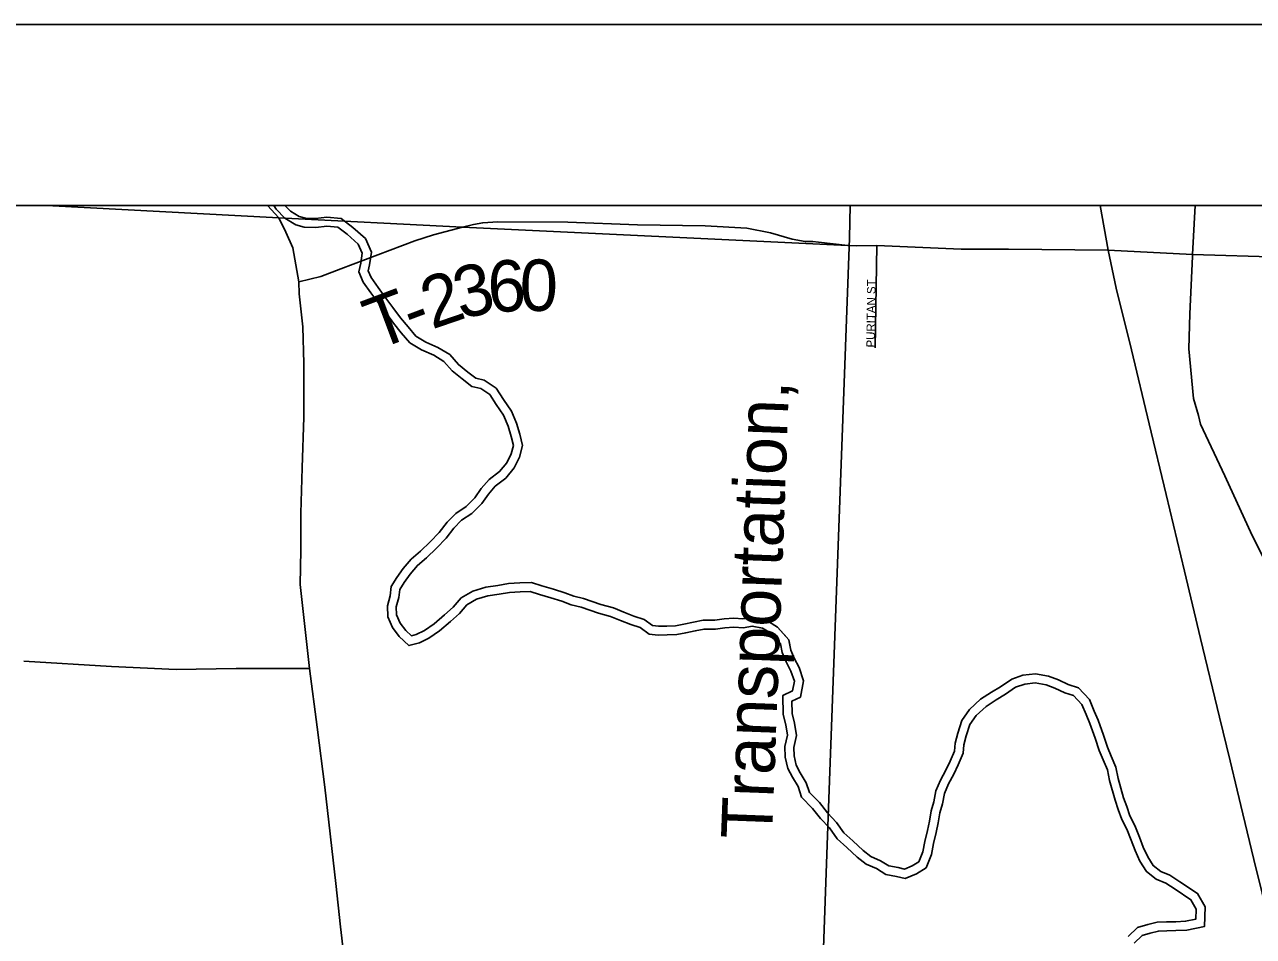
# Model space of a CAD drawing. Extents: x -22 to 431, y -18 to 160.
# Drawn here: x 323.477 to 324.836, y 159.112 to 160.12 of the extents above; entities that cross this region are included whole.
import ezdxf

# ---------------------------------------------------------------- set-up
doc = ezdxf.new("R2010")
doc.units = 0
for name, color, linetype in [('GM_X_Adjacent_County_Text', 7, 'Continuous'), ('GM_X_City_Street_Text', 7, 'Continuous'), ('GM_X_County_ROW', 7, 'Continuous'), ('GM_X_County_Subdivision', 7, 'Continuous'), ('GM_X_Major_Lake', 7, 'Continuous'), ('GM_X_Major_River_Text', 7, 'Continuous'), ('GM_X_Minor_River_Text', 7, 'Continuous'), ('GM_X_Rail_Line', 7, 'Continuous'), ('GM_X_Section', 7, 'Continuous'), ('GM_X_State_Location', 7, 'Continuous'), ('GM_X_Township_ROW', 7, 'Continuous'), ('GM_X_Township_Subdivision_Text', 7, 'Continuous')]:
    doc.layers.add(name, color=color, linetype=linetype)

msp = doc.modelspace()

# ---------------------------------------------------------------- linework, layer by layer
at = {"layer": 'GM_X_Adjacent_County_Text'}
for points in [[(324.7685, 159.8633), (324.7687, 159.8658), (324.7716, 159.9199)], [(325.1477, 159.1289), (325.1213, 159.1641), (325.057, 159.252), (325.0057, 159.3213), (324.9662, 159.3699), (324.9498, 159.3902), (324.9293, 159.4116), (324.9095, 159.4278), (324.896, 159.4378), (324.8897, 159.4458), (324.8837, 159.4573), (324.8346, 159.5549), (324.8044, 159.6209), (324.7775, 159.6781), (324.7754, 159.6876), (324.7699, 159.7066), (324.7645, 159.7613), (324.7657, 159.7999), (324.7685, 159.8633)]]:
    msp.add_lwpolyline(points, dxfattribs=at)
at = {"layer": 'GM_X_County_ROW'}
msp.add_lwpolyline([(323.8332, 159.0653), (323.8264, 159.1222), (323.8213, 159.1701), (323.8091, 159.2765), (323.8005, 159.3428), (323.792, 159.4078), (323.7817, 159.5007), (323.7825, 159.5388), (323.7825, 159.5795), (323.7841, 159.6298), (323.7859, 159.6857), (323.7859, 159.7452), (323.7848, 159.7857), (323.7809, 159.8223), (323.7804, 159.8356), (323.7739, 159.8729), (323.7661, 159.8902), (323.7583, 159.9062), (323.7457, 159.9199)], dxfattribs=at)
at = {"layer": 'GM_X_Major_River_Text'}
for p, q in [((323.5012, 159.9199), (323.7583, 159.9062)), ((323.7583, 159.9062), (323.9614, 159.896)), ((323.9614, 159.896), (324.3875, 159.8756)), ((324.3971, 159.8752), (324.3875, 159.8756)), ((324.3875, 159.8756), (324.3971, 159.8752)), ((324.4195, 159.8758), (324.3971, 159.8752)), ((324.4195, 159.8758), (324.513, 159.8717)), ((324.565, 159.8717), (324.513, 159.8717)), ((324.6754, 159.8703), (324.565, 159.8717)), ((324.7687, 159.8658), (324.6754, 159.8703)), ((324.7687, 159.8658), (325.4291, 159.8451))]:
    msp.add_line(p, q, dxfattribs=at)
at = {"layer": 'GM_X_Minor_River_Text'}
for points in [[(323.7804, 159.8356), (323.8048, 159.8412), (323.8268, 159.8498), (323.9088, 159.8809), (323.9293, 159.8876), (323.9614, 159.896), (323.9734, 159.8988), (323.9838, 159.9008), (324.0004, 159.9019), (324.0777, 159.9014), (324.1549, 159.8986), (324.2297, 159.8975), (324.2757, 159.8948), (324.302, 159.8895), (324.3258, 159.8826), (324.3405, 159.8802), (324.3487, 159.88), (324.3551, 159.8793), (324.3875, 159.8756), (324.3879, 159.8755)], [(324.3879, 159.8755), (324.3971, 159.8752), (324.4195, 159.8758), (324.513, 159.8717), (324.565, 159.8717)], [(323.4763, 159.416), (323.5733, 159.4102), (323.6446, 159.4068), (323.7112, 159.4078), (323.792, 159.4078)]]:
    msp.add_lwpolyline(points, dxfattribs=at)
at = {"layer": 'GM_X_Rail_Line'}
for points in [[(324.8245, 159.247), (324.8182, 159.2732), (324.8103, 159.3059), (324.7987, 159.3539), (324.7775, 159.4409), (324.7599, 159.5155), (324.7395, 159.6003), (324.7207, 159.6783), (324.7011, 159.7601), (324.6843, 159.8283), (324.6754, 159.8703), (324.6667, 159.9199)], [(325.0236, 158.268), (325.0178, 158.3353), (325.0111, 158.3892), (325.0083, 158.4105), (325.0062, 158.4257), (324.9949, 158.5051), (324.9839, 158.5695), (324.9706, 158.6339), (324.9581, 158.6937), (324.9437, 158.7535), (324.9274, 158.819), (324.909, 158.8939), (324.8914, 158.9704), (324.8757, 159.0378), (324.855, 159.1222), (324.8366, 159.1967), (324.8245, 159.247)]]:
    msp.add_lwpolyline(points, dxfattribs=at)
at = {"layer": 'GM_X_Section'}
msp.add_line((319.5549, 159.9199), (331.7949, 159.9199), dxfattribs=at)
msp.add_lwpolyline([(319.3549, 160.1199), (331.9949, 160.1199), (331.9949, 147.4799), (319.3549, 147.4799)], close=True, dxfattribs=at)
at = {"layer": 'GM_X_State_Location'}
msp.add_lwpolyline([(324.3484, 158.7568), (324.3659, 159.2438), (324.3892, 159.8839), (324.3902, 159.9199)], dxfattribs=at)
at = {"layer": 'GM_X_Township_ROW'}
msp.add_lwpolyline([(324.4179, 159.7623), (324.4195, 159.8758)], dxfattribs=at)
at = {"layer": 'GM_X_Township_Subdivision_Text'}
for points in [[(324.313, 159.4352), (324.3034, 159.4461), (324.2932, 159.4524), (324.2818, 159.4546), (324.272, 159.453), (324.2614, 159.4536), (324.2516, 159.4528), (324.241, 159.4515), (324.2285, 159.4514), (324.2187, 159.4494), (324.2082, 159.4474), (324.1983, 159.4454), (324.1878, 159.4449), (324.1776, 159.4448), (324.1677, 159.4458), (324.1578, 159.4533), (324.1476, 159.4566), (324.1362, 159.461), (324.1252, 159.4655), (324.1116, 159.4691), (324.0926, 159.4757), (324.0816, 159.4783), (324.0714, 159.4823), (324.0592, 159.486), (324.0464, 159.4897), (324.0361, 159.493), (324.0252, 159.4928), (324.0135, 159.492), (324.0018, 159.4899), (323.9893, 159.4883), (323.9769, 159.4844), (323.9663, 159.4782), (323.9581, 159.4686), (323.948, 159.4598), (323.936, 159.4494), (323.9243, 159.4414), (323.9138, 159.4363), (323.9021, 159.4332), (323.8914, 159.4433), (323.8838, 159.4531), (323.8787, 159.4651), (323.8783, 159.4773), (323.8812, 159.4883), (323.8826, 159.4985), (323.8886, 159.5085), (323.8957, 159.5184), (323.9046, 159.5287), (323.9148, 159.5375), (323.9256, 159.5479), (323.9357, 159.5582), (323.9443, 159.5697), (323.9541, 159.5793), (323.9654, 159.587), (323.9751, 159.5966), (323.9822, 159.6069), (323.9908, 159.6168), (324.0024, 159.6257), (324.0103, 159.6352), (324.0151, 159.6451), (324.0177, 159.6546), (324.0153, 159.6645), (324.0118, 159.6758), (324.0068, 159.6879), (323.9987, 159.6999), (323.9915, 159.7108), (323.9816, 159.7176), (323.9717, 159.7197), (323.9611, 159.728), (323.95, 159.7369), (323.9409, 159.7475), (323.9295, 159.7542), (323.9162, 159.7601), (323.9032, 159.7679), (323.8937, 159.7792), (323.8849, 159.7897), (323.8765, 159.8014), (323.8688, 159.8115), (323.86, 159.8232), (323.8516, 159.8352), (323.8466, 159.8465), (323.8488, 159.856), (323.8506, 159.8671), (323.8459, 159.8772), (323.8338, 159.8881), (323.8235, 159.896), (323.8114, 159.897), (323.7993, 159.8957), (323.7864, 159.8959), (323.777, 159.8985), (323.7648, 159.9059), (323.7553, 159.9157), (323.7528, 159.9199)], [(324.3204, 159.4417), (324.3098, 159.4537), (324.2968, 159.4618), (324.2819, 159.4646), (324.2715, 159.4629), (324.2613, 159.4635), (324.2506, 159.4626), (324.2404, 159.4613), (324.2275, 159.4612), (324.2168, 159.459), (324.2063, 159.457), (324.1971, 159.4552), (324.1875, 159.4547), (324.178, 159.4546), (324.1715, 159.4553), (324.1624, 159.4621), (324.1509, 159.4659), (324.1398, 159.4702), (324.1283, 159.4748), (324.1145, 159.4785), (324.0953, 159.4852), (324.0846, 159.4877), (324.0746, 159.4916), (324.062, 159.4954), (324.0492, 159.4991), (324.0376, 159.5028), (324.0247, 159.5027), (324.0122, 159.5017), (324.0003, 159.4997), (323.9872, 159.4979), (323.9728, 159.4934), (323.9599, 159.4859), (323.9511, 159.4756), (323.9415, 159.4672), (323.9299, 159.4572), (323.9194, 159.4499), (323.9103, 159.4456), (323.9048, 159.4441), (323.8987, 159.4499), (323.8923, 159.4581), (323.8885, 159.4673), (323.8881, 159.4762), (323.8908, 159.4863), (323.8921, 159.4952), (323.8968, 159.5031), (323.9034, 159.5123), (323.9116, 159.5218), (323.9214, 159.5303), (323.9325, 159.5409), (323.9432, 159.5518), (323.9518, 159.5632), (323.9603, 159.5717), (323.9716, 159.5794), (323.9827, 159.5902), (323.99, 159.6008), (323.9976, 159.6096), (324.0093, 159.6185), (324.0186, 159.6299), (324.0244, 159.6417), (324.0278, 159.6545), (324.0248, 159.6671), (324.0211, 159.6791), (324.0155, 159.6925), (324.0069, 159.7054), (323.9986, 159.7179), (323.9855, 159.7268), (323.976, 159.7289), (323.9672, 159.7357), (323.9569, 159.744), (323.9472, 159.7551), (323.934, 159.7629), (323.9207, 159.7688), (323.9097, 159.7755), (323.9012, 159.7855), (323.8927, 159.7957), (323.8844, 159.8072), (323.8767, 159.8174), (323.868, 159.829), (323.8602, 159.8401), (323.8569, 159.8475), (323.8584, 159.8541), (323.8608, 159.8684), (323.854, 159.8832), (323.84, 159.8957), (323.8272, 159.9055), (323.8113, 159.9068), (323.7989, 159.9055), (323.7878, 159.9058), (323.7809, 159.9076), (323.771, 159.9137), (323.7649, 159.9199)], [(324.3221, 159.4397), (324.3098, 159.4537), (324.2968, 159.4618), (324.2819, 159.4646), (324.2715, 159.4629), (324.2613, 159.4635), (324.2506, 159.4626), (324.2404, 159.4613), (324.2275, 159.4612), (324.2168, 159.459), (324.2063, 159.457), (324.1971, 159.4552), (324.1875, 159.4547), (324.178, 159.4546), (324.1715, 159.4553), (324.1624, 159.4621), (324.1509, 159.4659), (324.1398, 159.4702), (324.1283, 159.4748), (324.1145, 159.4785), (324.0953, 159.4852), (324.0846, 159.4877), (324.0746, 159.4916), (324.062, 159.4954), (324.0492, 159.4991), (324.0376, 159.5028), (324.0247, 159.5027), (324.0122, 159.5017), (324.0003, 159.4997), (323.9872, 159.4979), (323.9728, 159.4934), (323.9599, 159.4859), (323.9511, 159.4756), (323.9415, 159.4672), (323.9299, 159.4572), (323.9194, 159.4499), (323.9103, 159.4456), (323.9048, 159.4441), (323.8987, 159.4499), (323.8923, 159.4581), (323.8885, 159.4673), (323.8881, 159.4762), (323.8908, 159.4863), (323.8921, 159.4952), (323.8968, 159.5031), (323.9034, 159.5123), (323.9116, 159.5218), (323.9214, 159.5303), (323.9325, 159.5409), (323.9432, 159.5518), (323.9518, 159.5632), (323.9603, 159.5717), (323.9716, 159.5794), (323.9827, 159.5902), (323.99, 159.6008), (323.9976, 159.6096), (324.0093, 159.6185), (324.0186, 159.6299), (324.0244, 159.6417), (324.0278, 159.6545), (324.0248, 159.6671), (324.0211, 159.6791), (324.0155, 159.6925), (324.0069, 159.7054), (323.9986, 159.7179), (323.9855, 159.7268), (323.976, 159.7289), (323.9672, 159.7357), (323.9569, 159.744), (323.9472, 159.7551), (323.934, 159.7629), (323.9207, 159.7688), (323.9097, 159.7755), (323.9012, 159.7855), (323.8927, 159.7957), (323.8844, 159.8072), (323.8767, 159.8174), (323.868, 159.829), (323.8602, 159.8401), (323.8569, 159.8475), (323.8584, 159.8541), (323.8608, 159.8684), (323.854, 159.8832), (323.84, 159.8957), (323.8272, 159.9055), (323.8113, 159.9068), (323.7989, 159.9055), (323.7878, 159.9058), (323.7809, 159.9076), (323.771, 159.9137), (323.7649, 159.9199)], [(324.6977, 159.1113), (324.7078, 159.1213), (324.7191, 159.1248), (324.7297, 159.1272), (324.7399, 159.1277), (324.7501, 159.1278), (324.761, 159.1283), (324.7724, 159.1307), (324.7726, 159.1417), (324.7669, 159.1522), (324.7494, 159.1638), (324.7391, 159.1705), (324.7285, 159.175), (324.7178, 159.1832), (324.7105, 159.1949), (324.7052, 159.2066), (324.7009, 159.2179), (324.6959, 159.2303), (324.6905, 159.2409), (324.6866, 159.2519), (324.6831, 159.2621), (324.6769, 159.284), (324.6745, 159.2957), (324.6699, 159.307), (324.6656, 159.3172), (324.6609, 159.3308), (324.6551, 159.3471), (324.6509, 159.3569), (324.6462, 159.3682), (324.6371, 159.378), (324.6276, 159.3809), (324.6166, 159.3861), (324.6067, 159.3898), (324.5946, 159.3919), (324.5833, 159.3907), (324.5731, 159.3871), (324.5618, 159.3794), (324.5517, 159.3733), (324.5404, 159.3659), (324.5295, 159.356), (324.5224, 159.346), (324.5184, 159.3335), (324.5158, 159.3236), (324.5152, 159.3141), (324.5096, 159.3012), (324.5048, 159.2909), (324.4988, 159.2802), (324.4944, 159.2696), (324.4922, 159.2582), (324.4893, 159.2483), (324.4875, 159.2373), (324.4853, 159.2266), (324.4824, 159.2145), (324.4799, 159.2023), (324.474, 159.1875), (324.4634, 159.1809), (324.451, 159.1755), (324.4412, 159.178), (324.4294, 159.1802), (324.4192, 159.1865), (324.4078, 159.1913), (324.3979, 159.1992), (324.3864, 159.21), (324.3758, 159.2194), (324.3673, 159.2315), (324.3574, 159.242), (324.3486, 159.2532), (324.3364, 159.2656), (324.3325, 159.2773), (324.3264, 159.2875), (324.321, 159.2973), (324.3183, 159.3098), (324.3178, 159.3215), (324.3207, 159.3341), (324.3191, 159.3454), (324.3159, 159.3568), (324.3158, 159.378), (324.3263, 159.383), (324.3285, 159.3937), (324.3246, 159.405), (324.3192, 159.4152), (324.315, 159.4254), (324.313, 159.4352)], [(324.7043, 159.104), (324.713, 159.1126), (324.7217, 159.1153), (324.731, 159.1174), (324.7402, 159.1179), (324.7504, 159.118), (324.7623, 159.1185), (324.782, 159.1227), (324.7825, 159.1441), (324.7743, 159.1591), (324.7548, 159.172), (324.7437, 159.1792), (324.7335, 159.1835), (324.7252, 159.1899), (324.7192, 159.1995), (324.7142, 159.2104), (324.7101, 159.2215), (324.7048, 159.2344), (324.6995, 159.2448), (324.6959, 159.2551), (324.6925, 159.265), (324.6864, 159.2863), (324.6839, 159.2986), (324.6789, 159.3108), (324.6748, 159.3207), (324.6702, 159.3341), (324.6643, 159.3507), (324.6599, 159.3607), (324.6547, 159.3736), (324.6425, 159.3866), (324.6312, 159.3901), (324.6204, 159.3952), (324.6093, 159.3993), (324.5949, 159.4019), (324.5811, 159.4003), (324.5687, 159.396), (324.5565, 159.3877), (324.5465, 159.3816), (324.5344, 159.3738), (324.5221, 159.3625), (324.5136, 159.3505), (324.509, 159.3362), (324.5061, 159.3252), (324.5055, 159.3165), (324.5006, 159.3052), (324.496, 159.2954), (324.49, 159.2845), (324.4849, 159.2724), (324.4827, 159.2605), (324.4797, 159.2505), (324.4778, 159.239), (324.4757, 159.2288), (324.4728, 159.2166), (324.4704, 159.2052), (324.466, 159.1941), (324.4588, 159.1896), (324.4502, 159.1858), (324.4433, 159.1876), (324.433, 159.1895), (324.4237, 159.1953), (324.4128, 159.1999), (324.4043, 159.2066), (324.3931, 159.2173), (324.3831, 159.226), (324.375, 159.2377), (324.3649, 159.2484), (324.356, 159.2597), (324.345, 159.2709), (324.3415, 159.2815), (324.3349, 159.2924), (324.3303, 159.3008), (324.328, 159.3111), (324.3277, 159.3206), (324.3307, 159.3336), (324.3287, 159.3474), (324.3258, 159.3581), (324.3256, 159.3718), (324.335, 159.3763), (324.3386, 159.3943), (324.3336, 159.4089), (324.3281, 159.4194), (324.3244, 159.4283), (324.3221, 159.4397)], [(324.7043, 159.104), (324.713, 159.1126), (324.7217, 159.1153), (324.731, 159.1174), (324.7402, 159.1179), (324.7504, 159.118), (324.7623, 159.1185), (324.782, 159.1227), (324.7825, 159.1441), (324.7743, 159.1591), (324.7548, 159.172), (324.7437, 159.1792), (324.7335, 159.1835), (324.7252, 159.1899), (324.7192, 159.1995), (324.7142, 159.2104), (324.7101, 159.2215), (324.7048, 159.2344), (324.6995, 159.2448), (324.6959, 159.2551), (324.6925, 159.265), (324.6864, 159.2863), (324.6839, 159.2986), (324.6789, 159.3108), (324.6748, 159.3207), (324.6702, 159.3341), (324.6643, 159.3507), (324.6599, 159.3607), (324.6547, 159.3736), (324.6425, 159.3866), (324.6312, 159.3901), (324.6204, 159.3952), (324.6093, 159.3993), (324.5949, 159.4019), (324.5811, 159.4003), (324.5687, 159.396), (324.5565, 159.3877), (324.5465, 159.3816), (324.5344, 159.3738), (324.5221, 159.3625), (324.5136, 159.3505), (324.509, 159.3362), (324.5061, 159.3252), (324.5055, 159.3165), (324.5006, 159.3052), (324.496, 159.2954), (324.49, 159.2845), (324.4849, 159.2724), (324.4827, 159.2605), (324.4797, 159.2505), (324.4778, 159.239), (324.4757, 159.2288), (324.4728, 159.2166), (324.4704, 159.2052), (324.466, 159.1941), (324.4588, 159.1896), (324.4502, 159.1858), (324.4433, 159.1876), (324.433, 159.1895), (324.4237, 159.1953), (324.4128, 159.1999), (324.4043, 159.2066), (324.3931, 159.2173), (324.3831, 159.226), (324.375, 159.2377), (324.3649, 159.2484), (324.356, 159.2597), (324.345, 159.2709), (324.3415, 159.2815), (324.3349, 159.2924), (324.3303, 159.3008), (324.328, 159.3111), (324.3277, 159.3206), (324.3307, 159.3336), (324.3287, 159.3474), (324.3258, 159.3581), (324.3256, 159.3718), (324.335, 159.3763), (324.3386, 159.3943), (324.3336, 159.4089), (324.3281, 159.4194), (324.3244, 159.4283), (324.3226, 159.4372)]]:
    msp.add_lwpolyline(points, dxfattribs=at)

# ---------------------------------------------------------------- texts
at = {"layer": 'GM_X_City_Street_Text'}
for s, rotation, p in [('3', 13.804, (323.9594, 159.7936)), ('6', 2.9573, (323.9905, 159.8015)), ('0', 0.0156, (324.0247, 159.8033)), ('2', 18.8875, (323.9275, 159.7826)), ('T', 20.6167, (323.8663, 159.7596)), ('-', 20.5323, (323.9061, 159.7746))]:
    msp.add_text(s, height=0.0568, rotation=rotation, dxfattribs=at).set_placement(p)
at = {"layer": 'GM_X_County_Subdivision'}
msp.add_text('PURITAN ST', height=0.00947, rotation=89.2842, dxfattribs=at).set_placement((324.4174, 159.7628))
at = {"layer": 'GM_X_Major_Lake'}
msp.add_text('Transportation,', height=0.056463, rotation=87.8482, dxfattribs=at).set_placement((324.3036, 159.2184))

doc.saveas('drawing.dxf')
